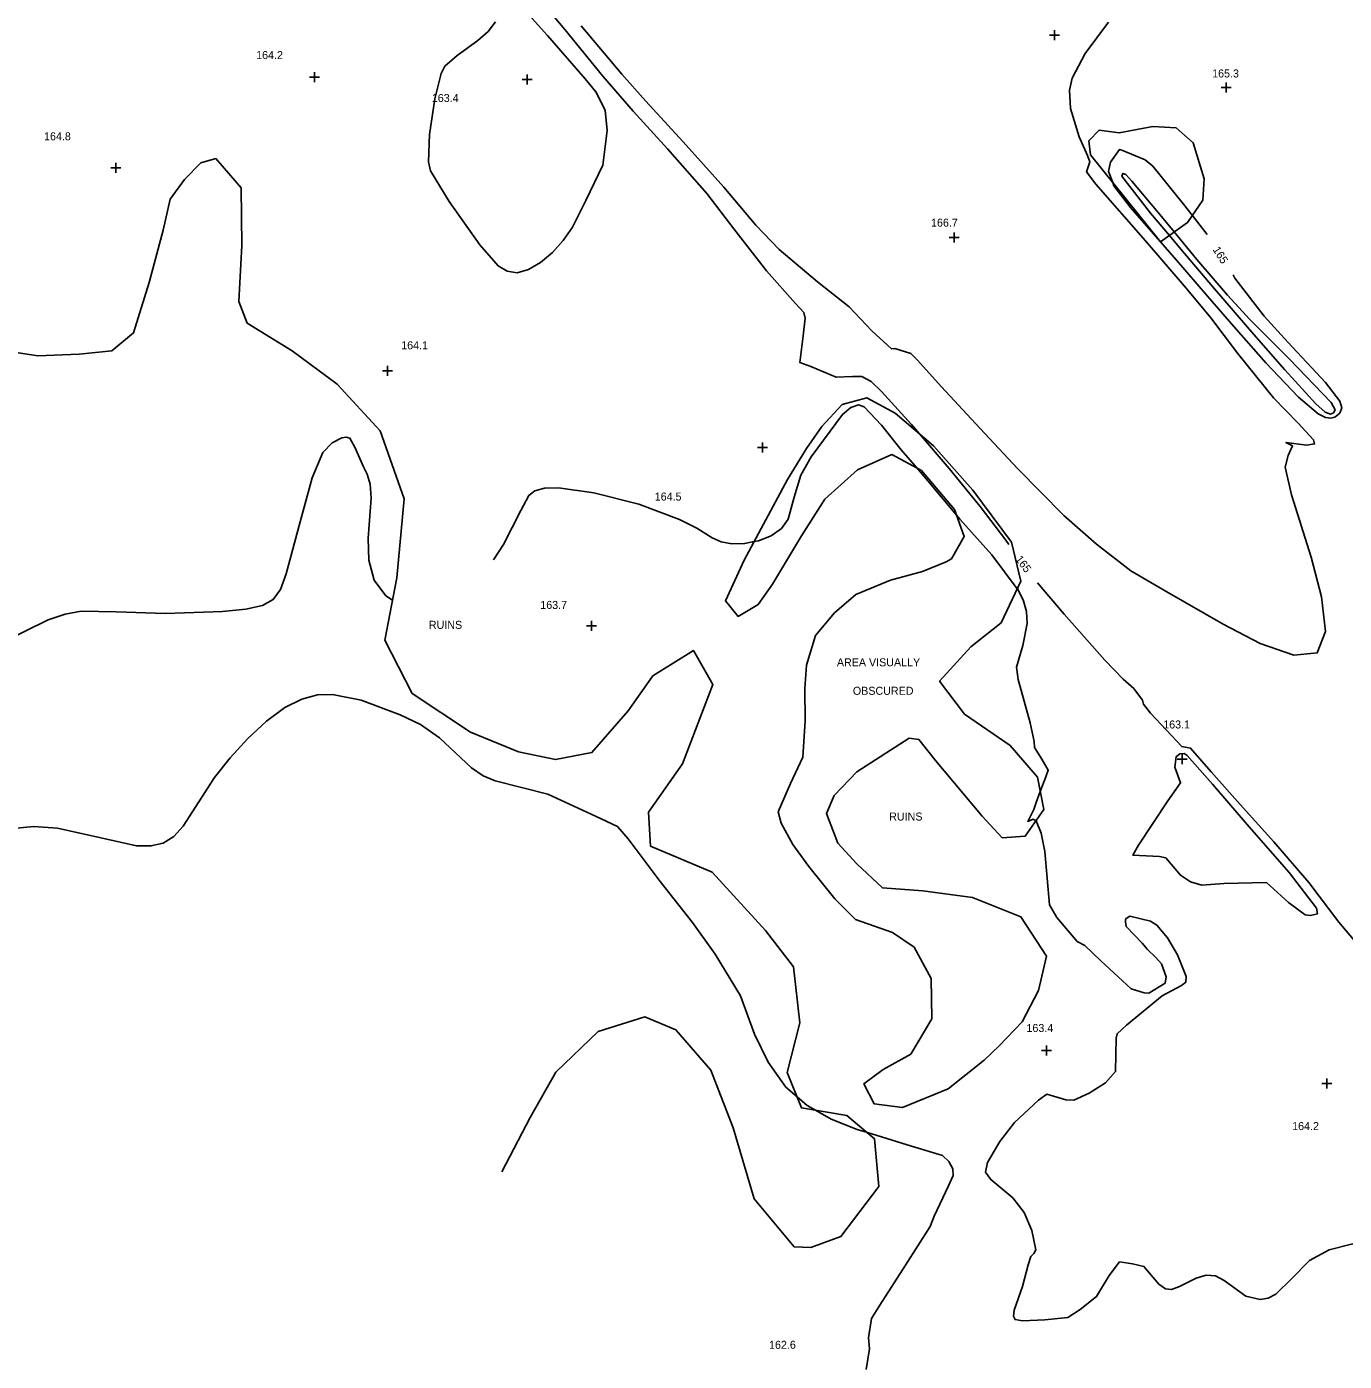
# Model space of a CAD drawing. Extents: x 1467615 to 2003689, y 770235 to 1108726.
# Drawn here: x 1999177.2 to 1999506.5, y 774676.6 to 775010.1 of the extents above; entities that cross this region are included whole.
import ezdxf

# ---------------------------------------------------------------- set-up
doc = ezdxf.new("R2010")
doc.units = 0
for name, color, linetype in [('RD_DTM_Major1', 7, 'Continuous'), ('RD_DTM_Major1_Lbl', 7, 'Continuous'), ('RD_DTM_Major2', 7, 'Continuous'), ('RD_DTM_Minor1', 7, 'Continuous'), ('RD_DTM_Minor2', 7, 'Continuous'), ('RD_DTM_Obscure', 7, 'Continuous'), ('RD_DTM_Spot_Elev', 7, 'Continuous'), ('RD_TX_Misc1', 7, 'Continuous')]:
    doc.layers.add(name, color=color, linetype=linetype)

msp = doc.modelspace()

# ---------------------------------------------------------------- linework, layer by layer
at = {"layer": 'RD_DTM_Major1'}
msp.add_line((1999468.49, 774962.94), (1999472.24, 774958.15), dxfattribs=at)
for points in [[(1999288.36, 775035.3), (1999289.21, 775034.45), (1999297.87, 775025.25), (1999302.73, 775020), (1999311.62, 775009.34), (1999321.2, 774997.68), (1999328.78, 774988.95), (1999337.29, 774979.59), (1999347.19, 774968.41), (1999353.89, 774959.53), (1999362.1, 774949.04), (1999369.28, 774940.87), (1999371.37, 774938.68), (1999371.71, 774937.27), (1999371.26, 774932.86), (1999370.39, 774926.17), (1999373.14, 774925.13), (1999379.44, 774922.46), (1999383.58, 774922.62), (1999385.89, 774922.63), (1999388.22, 774921.41), (1999390.78, 774918.95), (1999398.3, 774910.64), (1999400.29, 774908.32)], [(1999478.68, 774948.03), (1999479.15, 774947.27), (1999486.47, 774937.71), (1999492.36, 774931.27), (1999501.79, 774921.17), (1999505.36, 774916.53), (1999505.87, 774914.81), (1999505.4, 774913.54), (1999504.11, 774912.47), (1999503.1, 774912.21), (1999501.74, 774912.42), (1999499.93, 774913.33), (1999495, 774917.5), (1999486.86, 774926.04), (1999478.87, 774935.14), (1999472.3, 774942.77), (1999464.5, 774951.74), (1999453.08, 774964.92), (1999448.91, 774970.33), (1999448.59, 774971.13)], [(1999429.83, 774871.11), (1999436.49, 774863.27), (1999446.6, 774851.77), (1999451.23, 774847), (1999453.89, 774844.69), (1999456.01, 774841.77), (1999456.3, 774840.75), (1999458.04, 774838.51), (1999465.86, 774830.17), (1999468.06, 774829.8), (1999473.2, 774823.9), (1999480.46, 774815.71), (1999488.86, 774806.38), (1999497.59, 774796.21), (1999505.12, 774786.28), (1999512.84, 774777.15)]]:
    msp.add_lwpolyline(points, dxfattribs=at)
at = {"layer": 'RD_DTM_Major2'}
for points in [[(1999448.59, 774971.13), (1999447.53, 774973.87), (1999448.02, 774976.21), (1999450.28, 774979.38), (1999450.84, 774979.2), (1999456.71, 774976.81), (1999458.66, 774975.2), (1999466.29, 774965.74), (1999468.49, 774962.94)], [(1999400.29, 774908.32), (1999407.74, 774899.67), (1999415.43, 774890.2), (1999421.87, 774881.73), (1999422.63, 774880.71)]]:
    msp.add_lwpolyline(points, dxfattribs=at)
at = {"layer": 'RD_DTM_Minor1'}
msp.add_line((1999268.63, 774866.78), (1999268.74, 774866.71), dxfattribs=at)
for points in [[(1999298.25, 775018.03), (1999307.34, 775007.88), (1999316.74, 774997.07), (1999319.38, 774993.79), (1999321.73, 774989.18), (1999322.22, 774984.16), (1999321.16, 774975.43), (1999316.94, 774966.64), (1999313.54, 774960), (1999311.26, 774956.66), (1999308.55, 774953.62), (1999305.58, 774951.12), (1999302.58, 774949.37), (1999299.75, 774948.59)], [(1999299.75, 774948.59), (1999297.26, 774948.94), (1999295, 774950.33), (1999290.45, 774955.56), (1999282.75, 774966.36), (1999278.07, 774974.02), (1999277.56, 774976.3), (1999277.83, 774983.15), (1999279.21, 774992.01), (1999280.78, 774998.38), (1999281.68, 775000.17), (1999284.72, 775002.9), (1999289.92, 775006.65), (1999292.47, 775008.9), (1999294.36, 775011.26)], [(1999315.78, 775010.27), (1999325.91, 774998.17), (1999331.85, 774991.57), (1999341.2, 774981.33), (1999351.41, 774970.01), (1999359.37, 774960.48), (1999365.27, 774954.36), (1999374.84, 774946.31), (1999382.72, 774940.07), (1999388.39, 774934.06), (1999393.31, 774929.56), (1999394.12, 774929.67), (1999398.18, 774928.44), (1999399.7, 774926.84), (1999405.81, 774920.09), (1999414.28, 774910.93), (1999424.84, 774899.7), (1999436.4, 774887.93), (1999444.54, 774880.73), (1999453.1, 774874.07), (1999462.11, 774868.87), (1999476.2, 774860.74), (1999485.41, 774855.97), (1999493.84, 774853), (1999499.71, 774853.61), (1999501.75, 774858.96), (1999500.8, 774867.61), (1999498.21, 774877.49), (1999493.28, 774893.07), (1999491.72, 774900), (1999492.41, 774902.95), (1999493.57, 774905.33), (1999491.89, 774906.15), (1999497.1, 774905.47), (1999499.06, 774905.83), (1999498.76, 774906.82), (1999494.96, 774910.98), (1999488.77, 774917.37), (1999479.76, 774928.48), (1999473.11, 774937.29), (1999466.95, 774944.75), (1999456.79, 774956.53), (1999444.4, 774970.74), (1999442.08, 774973.82), (1999442.87, 774976.3), (1999442.29, 774977.89), (1999440.23, 774982.51), (1999438.08, 774989.64), (1999437.76, 774994.17), (1999438.43, 774997.2), (1999441.73, 775003.36), (1999447.51, 775011.18)], [(1999463.94, 774958.77), (1999469.58, 774951.92), (1999477.29, 774943), (1999482.87, 774936.88), (1999492.66, 774927.06), (1999503.19, 774916.16), (1999504.19, 774914.33), (1999503.77, 774913.56), (1999503.04, 774913.24), (1999501.72, 774913.71), (1999499.36, 774915.8), (1999491.61, 774924.33), (1999483.89, 774933.14), (1999474.07, 774944.56), (1999465.63, 774954.5), (1999462.75, 774957.91)], [(1999399.62, 774899.8), (1999402.42, 774896.56), (1999409.63, 774887.92)], [(1999293.84, 774876.83), (1999296.32, 774880.7), (1999300.65, 774889.14), (1999302.64, 774892.93), (1999304.19, 774894.13), (1999306.61, 774894.77), (1999310.11, 774894.81), (1999318.89, 774893.62), (1999330.15, 774890.77), (1999340.34, 774886.92), (1999344.63, 774884.74), (1999348.51, 774882.31), (1999350.71, 774881.36), (1999353.37, 774880.85), (1999356.58, 774880.93), (1999358.96, 774881.41)], [(1999424.72, 774869.62), (1999424.76, 774869.57), (1999426.18, 774866.87), (1999427.07, 774863.96), (1999427.21, 774860.97), (1999426.1, 774855.45), (1999424.52, 774850), (1999424.97, 774846.91), (1999427.98, 774836.15), (1999428.94, 774831.42), (1999429.02, 774829.94), (1999430.91, 774827.05), (1999432.48, 774824.27), (1999431.89, 774822.65), (1999430.49, 774818.98)], [(1999466.42, 774828.43), (1999467.23, 774827.93), (1999473.51, 774820.8), (1999482.71, 774810.12), (1999492.69, 774798.73), (1999499.56, 774789.78), (1999499.76, 774788.37), (1999498.02, 774787.94), (1999496.73, 774788.14), (1999492.54, 774791.25), (1999487.01, 774796.23), (1999476.39, 774795.98), (1999470.9, 774795.53), (1999468.08, 774796.42), (1999465.53, 774798.04), (1999463.19, 774800.78), (1999461.86, 774802.43), (1999460.26, 774802.75), (1999453.63, 774803.02), (1999455.03, 774805.55), (1999462.38, 774816.67), (1999465.57, 774821.14), (1999464.13, 774825.08), (1999464.43, 774827.63), (1999465.41, 774828.34), (1999466.42, 774828.43)], [(1999429.38, 774811.64), (1999429.44, 774811.6), (1999430.74, 774808.57), (1999431.61, 774803.98), (1999432.83, 774790.67), (1999434.61, 774787.51), (1999439.75, 774781.51), (1999441.64, 774780.51), (1999445.62, 774776.64), (1999453.21, 774769.66), (1999456.46, 774768.63), (1999457.66, 774768.55), (1999461.69, 774771.05), (1999461.94, 774772.64), (1999460.76, 774775.93), (1999459.35, 774777.52), (1999457.33, 774779.51), (1999455.93, 774781.09), (1999451.95, 774785.24), (1999451.77, 774786.39), (1999451.77, 774786.92), (1999451.95, 774787.27), (1999452.9, 774787.79), (1999458.05, 774786.55), (1999459.66, 774785.59), (1999462.27, 774782.37), (1999464.8, 774778.12), (1999466.99, 774772.74), (1999466.84, 774771.29), (1999465.82, 774770.48), (1999460.94, 774767.93), (1999452.06, 774760.57), (1999449.68, 774758.42), (1999449.48, 774757.34), (1999449.31, 774748.96), (1999446.82, 774746.16), (1999442.72, 774743.6), (1999438.92, 774741.86), (1999436.91, 774741.96), (1999432.09, 774743.31), (1999430.06, 774741.81), (1999424.03, 774736.27), (1999420.35, 774731.54), (1999417.26, 774726.26), (1999416.83, 774723.86), (1999418.12, 774721.99), (1999423.67, 774717.42), (1999426.45, 774713.77), (1999428.37, 774709.28), (1999429.4, 774704.45), (1999428.89, 774703.5), (1999428.1, 774702.79), (1999427.43, 774700.72), (1999426.08, 774695.3), (1999423.97, 774689.35), (1999423.8, 774687.88), (1999424.2, 774687.03), (1999426.06, 774686.68), (1999431.65, 774686.98), (1999437.4, 774687.51), (1999440.47, 774689.51), (1999444.57, 774692.77), (1999447.71, 774698.02), (1999450.32, 774701.48), (1999453.54, 774700.97), (1999456.41, 774700.29), (1999460.11, 774695.89), (1999461.8, 774694.73), (1999463.26, 774694.5), (1999465.28, 774695.26), (1999469.42, 774697.37), (1999471.99, 774698.1), (1999474.25, 774697.95), (1999476.43, 774696.8), (1999481.88, 774692.9), (1999485.47, 774692.03), (1999487.41, 774692.34), (1999489.39, 774693.33), (1999493.37, 774697.3), (1999497.77, 774701.76), (1999502.69, 774704.47), (1999508.61, 774705.91)], [(1999369.69, 774742.69), (1999372.26, 774740.47), (1999374.32, 774739.31)], [(1999387.27, 774733.73), (1999398.31, 774730.37), (1999406.02, 774727.98), (1999407.62, 774726.48), (1999408.67, 774724.65), (1999408.72, 774723.04), (1999407.54, 774720.45), (1999404, 774712.86), (1999402.95, 774710.25), (1999396.83, 774700.58), (1999390.37, 774690.61), (1999388.31, 774687.27), (1999387.57, 774682.47), (1999387.8, 774679.73), (1999386.96, 774674.57)]]:
    msp.add_lwpolyline(points, dxfattribs=at)
at = {"layer": 'RD_DTM_Minor2'}
for points in [[(1999462.75, 774957.91), (1999458.06, 774963.46), (1999450.88, 774972.75), (1999451.16, 774973.41), (1999451.87, 774973.13), (1999453.35, 774971.46), (1999459.95, 774963.61), (1999463.94, 774958.77)], [(1999358.96, 774881.41), (1999360.03, 774881.62), (1999363.26, 774882.89), (1999365.85, 774884.71), (1999367.49, 774887.04), (1999369.01, 774892.54), (1999370.61, 774898), (1999373.27, 774902.63), (1999381.1, 774913.17), (1999383.12, 774914.92), (1999385.05, 774915.55), (1999386.5, 774915.05), (1999390.8, 774910.5), (1999395.74, 774904.3), (1999399.62, 774899.8)], [(1999170.44, 774855.91), (1999182.55, 774861.83), (1999186.78, 774863.3), (1999190.78, 774863.99), (1999199.5, 774863.84), (1999211.82, 774863.47), (1999226.09, 774863.97), (1999231.95, 774864.55), (1999236.07, 774865.42), (1999238.77, 774866.9), (1999240.58, 774869.41), (1999242.05, 774873.35), (1999245.29, 774885.4), (1999248.52, 774897.38), (1999251.17, 774903.69), (1999253.52, 774906.09), (1999255.92, 774907.37), (1999257.01, 774907.54), (1999257.93, 774907.22), (1999259.18, 774904.99), (1999261.36, 774900.1), (1999262.29, 774898.23), (1999262.99, 774895.74), (1999263.23, 774892.27), (1999262.49, 774882.25), (1999262.64, 774876.77), (1999263.97, 774871.8), (1999266.91, 774867.88), (1999268.63, 774866.78)], [(1999409.63, 774887.92), (1999410.39, 774887.01), (1999418.39, 774878.07), (1999424.72, 774869.62)], [(1999172.87, 774809.63), (1999178.91, 774810.21), (1999184.83, 774809.83), (1999195.73, 774807.39), (1999204.63, 774805.43), (1999208.21, 774805.36), (1999211.3, 774806.07), (1999213.94, 774807.68), (1999216.25, 774810.28), (1999224.11, 774822.48), (1999227.99, 774827.4), (1999232.44, 774832.23), (1999237.12, 774836.55), (1999241.7, 774839.93), (1999245.94, 774842.06), (1999249.86, 774843.08), (1999253.56, 774843.22), (1999260.72, 774841.82), (1999270.48, 774838.1), (1999275.6, 774835.68), (1999280.31, 774832.35), (1999288.3, 774824.87), (1999291.24, 774822.88), (1999294.29, 774821.63), (1999307.39, 774818.34), (1999319.29, 774812.82), (1999324.82, 774810.26), (1999327.53, 774807.16), (1999335.47, 774796.47), (1999343.56, 774786.21), (1999349.2, 774778.35), (1999355.54, 774767.91), (1999359.1, 774758.37), (1999362.48, 774751.32), (1999366.93, 774745.07), (1999369.69, 774742.69)], [(1999430.49, 774818.98), (1999429.44, 774816.24), (1999428.89, 774814.45), (1999427.35, 774811.51), (1999428.72, 774812.06), (1999429.38, 774811.64)], [(1999374.32, 774739.31), (1999378.24, 774737.1), (1999384.75, 774734.49), (1999387.27, 774733.73)]]:
    msp.add_lwpolyline(points, dxfattribs=at)
at = {"layer": 'RD_DTM_Obscure'}
for points in [[(1999460.54, 774956.33), (1999443.02, 774978.04), (1999442.6, 774981.56), (1999445.2, 774984.25), (1999450.2, 774983.52), (1999458.65, 774985.15), (1999464.43, 774984.77), (1999468.73, 774981.06), (1999471.43, 774972.03), (1999471.12, 774966.76), (1999467.25, 774961.13), (1999460.54, 774956.33)], [(1999166.93, 774929.86), (1999179.94, 774927.86), (1999190.3, 774928.22), (1999198.4, 774929.09), (1999203.83, 774933.57), (1999207.81, 774946.17), (1999211.24, 774959.19), (1999213.03, 774966.94), (1999216.57, 774971.91), (1999220.65, 774976.08), (1999224.44, 774977.11), (1999230.73, 774969.84), (1999230.95, 774955.36), (1999230.15, 774941.41), (1999232.23, 774936.02), (1999243.53, 774929.04), (1999254.75, 774920.72), (1999265.49, 774909.07), (1999271.52, 774892.12), (1999269.71, 774872.37), (1999266.7, 774856.81), (1999273.51, 774843.47), (1999288.1, 774833.8), (1999300.1, 774828.89), (1999309.29, 774826.92), (1999318.41, 774828.7), (1999327.46, 774839.11), (1999333.62, 774847.87), (1999343.78, 774854.19), (1999348.66, 774845.66), (1999341.08, 774825.84), (1999332.61, 774813.76), (1999333.08, 774805.29), (1999348.45, 774798.83), (1999361.82, 774784.23), (1999368.8, 774775.18), (1999370.39, 774761.16), (1999367.27, 774748.75), (1999370.8, 774739.9), (1999382.13, 774738), (1999389.1, 774732.21), (1999390.14, 774720.23), (1999380.67, 774707.79), (1999373.11, 774705.06), (1999368.98, 774705.2), (1999359, 774717.21), (1999353.77, 774734.92), (1999348.17, 774749.37), (1999339.42, 774759.39), (1999331.63, 774762.63), (1999319.99, 774758.98), (1999309.42, 774748.83), (1999303, 774737.49), (1999295.88, 774723.89)], [(1999364.98, 774813.89), (1999368.08, 774821), (1999371.15, 774827.54), (1999371.77, 774836.62), (1999371.66, 774844.68), (1999372.09, 774850.51), (1999374.34, 774857.96), (1999379.08, 774863.63), (1999384.43, 774868.22), (1999393.08, 774871.75), (1999401.08, 774873.97), (1999406.98, 774876.32), (1999408.27, 774877.11), (1999411.48, 774882.69), (1999409.08, 774889.46), (1999400.8, 774899.17), (1999393.43, 774903.15), (1999384.85, 774899.32), (1999376.65, 774892.01), (1999370.83, 774882.83), (1999363.6, 774870.76), (1999359.95, 774865.69), (1999354.97, 774862.71), (1999351.84, 774866.64), (1999356.45, 774876.75), (1999367.32, 774896.96), (1999372.09, 774904.66), (1999375.87, 774910.2), (1999380.99, 774915.67), (1999387.14, 774917.34), (1999394.21, 774913.47), (1999403.83, 774905.32), (1999413.67, 774894.28), (1999423.29, 774881.24), (1999425.61, 774871.5), (1999420.69, 774861.11), (1999413.14, 774855.11), (1999405.34, 774846.53), (1999411.59, 774838.3), (1999422.95, 774830.44), (1999429.8, 774822.55), (1999431.35, 774814.48), (1999426.74, 774807.83), (1999420.95, 774807.4), (1999415.98, 774812.78), (1999404.29, 774826.71), (1999400.18, 774831.94), (1999397.7, 774832.28), (1999384.63, 774823.91), (1999379.01, 774817.99), (1999377.02, 774813.5), (1999379.86, 774806.03), (1999384.65, 774800.86), (1999391.03, 774794.92), (1999401.16, 774794.15), (1999413.55, 774792.47), (1999425.66, 774787.64), (1999432.02, 774777.86), (1999430.08, 774769.23), (1999425.98, 774761.39), (1999420.25, 774755.38), (1999416.49, 774751.86), (1999407.43, 774744.69), (1999396.02, 774739.97), (1999388.97, 774740.96), (1999386.37, 774745.91), (1999391.19, 774749.47), (1999398.13, 774753.3), (1999403.35, 774762.12), (1999403.26, 774772.22), (1999399, 774780.05), (1999393.54, 774783.73), (1999384.31, 774786.95), (1999379.14, 774792.15), (1999372.68, 774800.21), (1999368.68, 774805.72), (1999365.72, 774811.08), (1999364.98, 774813.89)]]:
    msp.add_lwpolyline(points, dxfattribs=at)
at = {"layer": 'RD_DTM_Spot_Elev'}
for p, q in [((1999432.83, 775007.92), (1999435.33, 775007.92)), ((1999434.08, 775006.67), (1999434.08, 775009.17)), ((1999249.09, 774996.21), (1999249.09, 774998.71)), ((1999302.22, 774995.64), (1999302.22, 774998.14)), ((1999247.84, 774997.46), (1999250.34, 774997.46)), ((1999300.97, 774996.89), (1999303.47, 774996.89)), ((1999475.67, 774994.88), (1999478.17, 774994.88)), ((1999476.92, 774993.63), (1999476.92, 774996.13)), ((1999198.17, 774974.84), (1999200.67, 774974.84)), ((1999199.42, 774973.59), (1999199.42, 774976.09)), ((1999409, 774956.14), (1999409, 774958.64)), ((1999407.75, 774957.39), (1999410.25, 774957.39)), ((1999267.36, 774922.85), (1999267.36, 774925.35)), ((1999266.11, 774924.1), (1999268.61, 774924.1)), ((1999359.78, 774904.92), (1999362.28, 774904.92)), ((1999361.03, 774903.67), (1999361.03, 774906.17)), ((1999318.34, 774859.08), (1999318.34, 774861.58)), ((1999317.09, 774860.33), (1999319.59, 774860.33)), ((1999465.98, 774825.79), (1999465.98, 774828.29)), ((1999464.73, 774827.04), (1999467.23, 774827.04)), ((1999432.02, 774753.01), (1999432.02, 774755.51)), ((1999430.77, 774754.26), (1999433.27, 774754.26)), ((1999500.88, 774745.98), (1999503.38, 774745.98)), ((1999502.13, 774744.73), (1999502.13, 774747.23))]:
    msp.add_line(p, q, dxfattribs=at)

# ---------------------------------------------------------------- texts
at = {"layer": 'RD_DTM_Major1_Lbl'}
for rotation, p in [(302.1455, (1999473.5, 774954.38)), (306.7595, (1999424.15, 774877.01))]:
    msp.add_text('165', height=2, rotation=rotation, dxfattribs=at).set_placement(p)
at = {"layer": 'RD_DTM_Spot_Elev'}
for s, p in [('164.2', (1999234.51, 775001.98)), ('165.3', (1999473.45, 774997.38)), ('163.4', (1999278.42, 774991.25)), ('164.8', (1999181.5, 774981.68)), ('166.7', (1999403.19, 774960.1)), ('164.1', (1999270.77, 774929.45)), ('164.5', (1999334.13, 774891.66)), ('163.7', (1999305.53, 774864.59)), ('163.1', (1999461.22, 774834.71)), ('163.4', (1999427.04, 774758.87)), ('164.2', (1999493.45, 774734.36)), ('162.6', (1999362.7, 774679.71))]:
    msp.add_text(s, height=2, dxfattribs=at).set_placement(p)
at = {"layer": 'RD_TX_Misc1'}
for s, p in [('RUINS', (1999277.68, 774859.61)), ('AREA VISUALLY', (1999379.66, 774850.24)), ('OBSCURED', (1999383.65, 774843.13)), ('RUINS', (1999392.73, 774811.71))]:
    msp.add_text(s, height=2, dxfattribs=at).set_placement(p)

doc.saveas('drawing.dxf')
